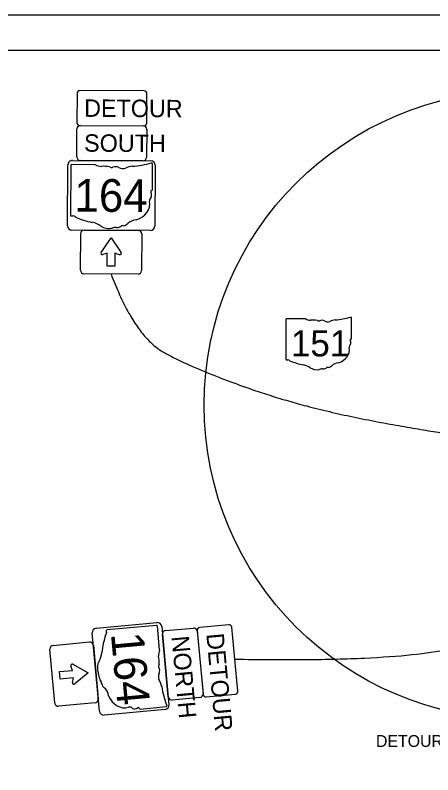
# Model space of a CAD drawing. Extents: x -740 to 1519, y 0 to 440.
# Drawn here: x 350.9 to 470.5, y 222.2 to 440 of the extents above; entities that cross this region are included whole.
import ezdxf

# ---------------------------------------------------------------- set-up
doc = ezdxf.new("R2010")
doc.units = 0
for name, color, linetype in [('GM_X_County_Road_Text', 7, 'Continuous'), ('GM_X_Minor_River', 7, 'Continuous'), ('GM_X_Section', 7, 'Continuous'), ('SH_Border', 7, 'Continuous'), ('SH_Cut_Line', 7, 'Continuous'), ('SH_Data', 7, 'Continuous')]:
    doc.layers.add(name, color=color, linetype=linetype)

msp = doc.modelspace()

# ---------------------------------------------------------------- linework, layer by layer
at = {"layer": 'GM_X_County_Road_Text'}
for p, q in [((434.11, 352.95), (428.62, 352.95)), ((447.19, 347.28), (447.19, 353.24)), ((428.44, 352.76), (428.44, 341.37)), ((447.18, 347.28), (447.19, 347.28))]:
    msp.add_line(p, q, dxfattribs=at)
for centre, major_axis, start_param, end_param in [((428.65, 352.78), (0.217, 0), 1.712693, 3.28349), ((435.42, 354.28), (2.11, 0), 4.042523, 4.731795), ((440.51, 368.48), (19.88, 0), 4.814394, 5.042369), ((446.98, 353.26), (0.209, 0), 6.141152, 7.989035), ((436.12, 346.56), (7.56, 0), 1.404758, 1.657858), ((437.83, 352.84), (0.608, 0), 3.836095, 5.185415), ((438.73, 351.53), (1.26, 0), 0.950623, 2.079405), ((440.36, 353.33), (1.52, 0), 4.081561, 5.145723), ((443.04, 349.48), (4, 0), 1.699011, 2.107814), ((447.14, 346.84), (0.323, 0), 1.883978, 3.671073), ((445.08, 346.09), (1.94, 0), 5.934695, 6.695948), ((446.96, 347.26), (0.223, 0), 5.05454, 6.418171), ((441.62, 344.03), (4.97, 0), 5.101752, 6.440018), ((447.93, 344.79), (1.41, 0), 2.387724, 3.262537), ((428.65, 341.35), (0.219, 0), 3.00124, 4.508301), ((428.69, 342.51), (1.67, 0), 4.665946, 4.897461), ((429.03, 340.72), (0.603, 0), 0.519207, 1.627899), ((436.64, 350.95), (14.36, 0), 4.195997, 4.488961), ((432.36, 336.26), (4.49, 0), 0.823519, 1.323587), ((443.72, 338.18), (2.72, 0), 1.647645, 2.488434), ((437.22, 340.66), (2.85, 0), 4.026481, 4.996735), ((438.87, 336.72), (2.34, 0), 1.495662, 1.94098), ((439.07, 339.81), (1.52, 0), 4.691044, 5.507374), ((440.45, 338.71), (0.428, 0), 1.147584, 2.315152), ((440.27, 340.27), (1.61, 0), 4.937069, 5.64225)]:
    msp.add_ellipse(centre, major_axis=major_axis, ratio=0.8, start_param=start_param, end_param=end_param, dxfattribs=at)
at = {"layer": 'GM_X_Minor_River'}
for p, q in [((368.53, 399.38), (368.57, 407.38)), ((369.57, 408.37), (387.57, 408.28)), ((388.57, 407.27), (388.53, 399.27)), ((366.79, 396.92), (366.72, 382.69)), ((373.89, 397.12), (367.03, 397.16)), ((387.52, 398.28), (369.52, 398.37)), ((390.19, 389.94), (390.23, 397.39)), ((390.19, 389.95), (390.19, 389.94)), ((369.6, 366.87), (369.66, 377.37)), ((370.66, 378.37), (386.16, 378.28)), ((387.16, 377.28), (387.1, 366.78)), ((375.54, 372.01), (378.4, 376.14)), ((378.4, 376.14), (381.17, 372.04)), ((377.28, 371.77), (376, 371.38)), ((377.26, 368.02), (377.28, 371.77)), ((379.47, 371.76), (379.45, 368.01)), ((380.75, 371.35), (379.47, 371.76)), ((379.45, 368.01), (377.26, 368.02)), ((386.1, 365.78), (370.6, 365.87)), ((391.36, 265.07), (377.19, 263.76)), ((392.26, 258.03), (391.63, 264.86)), ((393.98, 263.59), (401.95, 264.32)), ((394.73, 244.58), (393.08, 262.5)), ((403.03, 263.42), (404.69, 245.5)), ((361.73, 259.35), (372.19, 260.32)), ((373.28, 259.41), (374.7, 243.98)), ((362.26, 242.83), (360.83, 258.26)), ((367.35, 252.18), (366.84, 253.42)), ((367.43, 253.95), (371.81, 251.5)), ((363.62, 251.84), (367.35, 252.18)), ((363.82, 249.66), (363.62, 251.84)), ((371.81, 251.5), (368.01, 248.34)), ((367.55, 250), (363.82, 249.66)), ((367.28, 248.69), (367.55, 250)), ((403.79, 244.41), (395.82, 243.67)), ((373.8, 242.89), (363.34, 241.93)), ((386.7, 241.1), (394.11, 241.79)), ((386.7, 241.11), (386.7, 241.1))]:
    msp.add_line(p, q, dxfattribs=at)
for points in [[(387.83, 418.28), (369.43, 418.37)], [(368.62, 417.58), (368.58, 409.18)], [(388.58, 409.07), (388.62, 417.47)], [(369.37, 408.37), (387.77, 408.28)], [(365.92, 379.64), (366.01, 397.14)], [(367.27, 398.39), (389.77, 398.26)], [(391.01, 397.01), (390.92, 379.51)], [(389.66, 378.26), (367.16, 378.39)], [(374.08, 264.26), (391.51, 265.87)], [(392.87, 264.74), (394.94, 242.34)], [(403.02, 263.62), (404.71, 245.3)], [(412.1, 265.26), (403.74, 264.49)], [(414.67, 246.22), (412.97, 264.54)], [(375.03, 240.49), (372.95, 262.9)], [(405.58, 244.58), (413.94, 245.35)], [(393.81, 240.98), (376.39, 239.36)]]:
    msp.add_lwpolyline(points, dxfattribs=at)
for centre, radius, start, end in [((369.42, 417.57), 0.8, 89.6918, 179.6918), ((387.82, 417.48), 0.8, 359.6918, 89.6918), ((369.57, 407.37), 1, 89.6918, 179.6918), ((369.38, 409.17), 0.8, 179.6918, 269.6918), ((387.57, 407.28), 1, 359.6918, 89.6918), ((387.78, 409.08), 0.8, 269.6918, 359.6918), ((369.53, 399.37), 1, 179.6918, 269.6918), ((387.53, 399.28), 1, 269.6918, 359.6918), ((367.26, 397.14), 1.25, 89.6918, 179.6918), ((389.76, 397.01), 1.25, 359.6918, 89.6918), ((367.17, 379.64), 1.25, 179.6918, 269.6918), ((389.67, 379.51), 1.25, 269.6918, 359.6918), ((370.66, 377.37), 1, 89.6918, 179.6918), ((386.16, 377.28), 1, 359.6918, 89.6918), ((375.88, 371.78), 0.417, 145.103, 286.8964), ((380.88, 371.75), 0.417, 252.4872, 44.7014), ((370.6, 366.87), 1, 179.6918, 269.6918), ((386.1, 366.78), 1, 269.6918, 359.6918), ((391.62, 264.63), 1.25, 5.2824, 95.2824), ((374.2, 263.01), 1.25, 95.2824, 185.2824), ((394.07, 262.59), 1, 95.2824, 185.2824), ((402.04, 263.33), 1, 5.2824, 95.2824), ((403.81, 263.69), 0.8, 95.2824, 185.2824), ((412.18, 264.47), 0.8, 5.2824, 95.2824), ((361.83, 258.36), 1, 95.2824, 185.2824), ((372.28, 259.32), 1, 5.2824, 95.2824), ((367.22, 253.58), 0.417, 60.6936, 202.487), ((367.68, 248.6), 0.417, 168.0778, 320.2919), ((413.87, 246.15), 0.8, 275.2824, 5.2824), ((373.71, 243.89), 1, 275.2824, 5.2824), ((395.73, 244.67), 1, 185.2824, 275.2824), ((403.69, 245.41), 1, 275.2824, 5.2824), ((405.51, 245.37), 0.8, 185.2824, 275.2824), ((363.25, 242.92), 1, 185.2824, 275.2824), ((393.7, 242.22), 1.25, 275.2824, 5.2824), ((376.27, 240.61), 1.25, 185.2824, 275.2824)]:
    msp.add_arc(centre, radius, start, end, dxfattribs=at)
for centre, major_axis, start_param, end_param in [((367.06, 396.95), (0.272, -0.001), 1.712693, 3.28349), ((375.53, 398.77), (2.63, -0.01), 4.042523, 4.731795), ((376.35, 389.12), (9.45, -0.05), 1.404758, 1.657858), ((378.54, 396.96), (0.76, -0.004), 3.836095, 5.185415), ((379.65, 395.31), (1.58, -0.01), 0.950623, 2.079405), ((381.7, 397.55), (1.9, -0.01), 4.081561, 5.145723), ((385.03, 392.72), (5, -0.03), 1.699011, 2.107814), ((381.99, 416.48), (24.85, -0.13), 4.814394, 5.042369), ((389.97, 397.42), (0.261, -0.001), 6.141152, 7.989035), ((389.91, 389.92), (0.279, -0.002), 5.05454, 6.418171), ((391.11, 386.82), (1.76, -0.01), 2.387724, 3.262537), ((390.13, 389.4), (0.404, -0.002), 1.883978, 3.671073), ((387.56, 388.47), (2.42, -0.01), 5.934695, 6.695948), ((383.22, 385.92), (6.22, -0.03), 5.101752, 6.440018), ((366.99, 382.65), (0.274, -0.001), 3.00124, 4.508301), ((367.04, 384.11), (2.09, -0.01), 4.665946, 4.897461), ((367.45, 381.86), (0.754, -0.004), 0.519207, 1.627899), ((377.04, 394.6), (17.95, -0.1), 4.195997, 4.488961), ((385.8, 378.59), (3.4, -0.02), 1.647645, 2.488434), ((371.59, 376.27), (5.62, -0.03), 0.823519, 1.323587), ((377.69, 381.73), (3.56, -0.02), 4.026481, 4.996735), ((379.72, 376.8), (2.93, -0.02), 1.495662, 1.94098), ((380, 380.66), (1.9, -0.01), 4.691044, 5.507374), ((381.72, 379.27), (0.535, -0.003), 1.147584, 2.315152), ((381.5, 381.23), (2.01, -0.01), 4.937069, 5.64225), ((377.18, 263.49), (0.025, -0.273), 3.00124, 4.508301), ((378.64, 263.58), (0.19, -2.08), 4.665946, 4.897461), ((391.42, 264.81), (0.025, -0.27), 1.712693, 3.28349), ((390.05, 254.65), (1.65, -17.87), 4.195997, 4.488961), ((376.44, 262.95), (0.069, -0.751), 0.519207, 1.627899), ((371.28, 258.29), (0.52, -5.59), 0.823519, 1.323587), ((394.05, 256.55), (0.24, -2.62), 4.042523, 4.731795), ((377.31, 252.75), (0.33, -3.55), 4.026481, 4.996735), ((384.53, 254.8), (0.87, -9.41), 1.404758, 1.657858), ((392.55, 253.38), (0.07, -0.757), 3.836095, 5.185415), ((391.01, 252.12), (0.15, -1.57), 0.950623, 2.079405), ((372.6, 250.24), (0.27, -2.92), 1.495662, 1.94098), ((393.44, 250.3), (0.17, -1.89), 4.081561, 5.145723), ((376.47, 250.34), (0.17, -1.89), 4.691044, 5.507374), ((375.25, 248.5), (0.049, -0.532), 1.147584, 2.315152), ((377.18, 248.91), (0.18, -2), 4.937069, 5.64225), ((388.96, 246.51), (0.46, -4.98), 1.699011, 2.107814), ((374.97, 244.37), (0.31, -3.39), 1.647645, 2.488434), ((412.31, 251.86), (2.29, -24.75), 4.814394, 5.042369), ((382.01, 247.66), (0.57, -6.19), 5.101752, 6.440018), ((383.68, 239.89), (0.16, -1.76), 2.387724, 3.262537), ((394.12, 242.05), (0.024, -0.26), 6.141152, 7.989035), ((384.98, 243.59), (0.22, -2.41), 5.934695, 6.695948), ((386.15, 241.11), (0.037, -0.402), 1.883978, 3.671073), ((386.65, 241.38), (0.026, -0.278), 5.05454, 6.418171)]:
    msp.add_ellipse(centre, major_axis=major_axis, ratio=0.8, start_param=start_param, end_param=end_param, dxfattribs=at)
at = {"layer": 'SH_Border'}
msp.add_lwpolyline([(30, 430), (670, 430), (670, 10), (30, 10)], close=True, dxfattribs=at)
at = {"layer": 'SH_Cut_Line'}
msp.add_lwpolyline([(0, 0), (680, 0), (680, 440), (0, 440)], close=True, dxfattribs=at)
at = {"layer": 'SH_Data'}
msp.add_circle((495, 328.25), 90, dxfattribs=at)
for points in [[(378.35, 365.83), (385, 348.06), (402, 338.57), (434.58, 327.18), (475.36, 319.62), (495.67, 317.59), (498.24, 330.34)], [(413.82, 255.38), (478.14, 254.29), (492.33, 270.79), (501.43, 314.73), (502.79, 325.82)]]:
    msp.add_open_spline(points, degree=2, dxfattribs=at)

# ---------------------------------------------------------------- texts
at = {"layer": 'GM_X_County_Road_Text'}
msp.add_text('151', height=7.5, dxfattribs=at).set_placement((429.84, 342.18))
at = {"layer": 'GM_X_Minor_River'}
for s, height, rotation, p in [('DETOUR', 5, 359.6918, (370.62, 410.87)), ('SOUTH', 5, 359.6918, (370.62, 400.87)), ('164', 9.375, 359.6918, (367.87, 383.68)), ('164', 9.375, 275.2824, (378.29, 262.71)), ('NORTH', 5, 275.2824, (395.65, 261.87)), ('DETOUR', 5, 275.2824, (405.62, 262.62))]:
    msp.add_text(s, height=height, rotation=rotation, dxfattribs=at).set_placement(p)
at = {"layer": 'GM_X_Section'}
msp.add_text('DETOUR INTERSECTION DETAIL 2', height=3.4, dxfattribs=at).set_placement((454.21, 230.23))

doc.saveas('drawing.dxf')
